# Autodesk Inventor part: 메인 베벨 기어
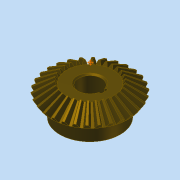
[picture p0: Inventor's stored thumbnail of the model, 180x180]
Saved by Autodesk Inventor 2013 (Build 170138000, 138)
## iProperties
Created: 2016-04
Part Number: 메인 베벨 기어
Material: 강철, 탄소
Document SubType Name: 판금
Designer: mdu
Categories: <?xml version="1.0" encoding="UTF-16"?> <MemberInstance><Categories><FamilyTemplate><FamilyTemplateParameter ValueType="xs:double" Id="1" ObjectReferenceKey="da
Mass: 269.926 g
Surface Area: 108.837 cm^2
Volume: 34.2981 cm^3
Density: 7.87 g/cm^3
Sheet Metal Rule: 기본값
CustomPartVersion: 1
Author: mdu
Revision Number: 1
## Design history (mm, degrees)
node "맨 위 점"
node "메쉬 평면2"
sketch "톱니 본체 스케치"
  geometry: L1 (0, 0)-(28.669, -21.997); L2 (28.669, -21.997)-(31.109, -18.336); L3 (31.109, -18.336)-(0, 0); L4 (30, -20)-(0, 0); L5 (17.219, -13.212)-(18.685, -11.013); L6 (28.669, -21.997)-(17.219, -13.212); L7 (31.109, -18.336)-(18.685, -11.013); L8 (0, -39.387)-(0, 6.564) reference; L9 (0, -20)-(31.109, -20)
  constraints: 16 end point, 4 point on line, 3 perpendicular, 2 collinear, 1 horizontal alignment, 1 vertical alignment
  dimensions: "d0" = 60 diameter of L4.start L8 (= da_de); "d1" = 57.33744 diameter of L1.end L8 (= da_dfe); "d2" = 62.2188 diameter of L2.end L8 (= da_dae); "d3" = 14.4 distance between parallel lines of L2 L5 (= da_b); "d4" = 18.3359 vertical distance of L2.end L1.start (= da_ve)
revolve "톱니 본체" sketch "톱니 본체 스케치" stored, may be unused: angle "d5" = 90 deg
node "시작점"
node "톱니 평면"
sketch "시작 스케치"
  geometry: L1 (0, -23.505)-(0, 10.645) reference; L2 (-0.709, -2.928)-(0.709, -2.928); A1 r 19.188 centre (-19.457, -7.014) between (-0.709, -2.928) and (-3.232, 3.229); A2 r 19.188 centre (19.457, -7.014) between (3.232, 3.229) and (0.709, -2.928); A3 r 57.403 centre (0, -54.083) between (3.232, 3.229) and (-3.232, 3.229); 1 further point
  constraints: 6 point on circle, 3 centre point, 3 symmetric about line, 2 end point, 1 coincident, 1 perpendicular, 1 other
  dimensions: "d7" = 19.18795 radius of A1 (= fd_rr); "d8" = 19.45712 horizontal distance of point (0, -54.083) A1.centre (= fd_x); "d9" = 47.06905 vertical distance of point (0, -54.083) A1.centre (= fd_y); "d57" = 57.40327 radius of A3 (= 0.5 x fd_dva + 0.3 x da_he); "d58" = 51.15527 distance from line of A3.centre L2 (= 0.5 x fd_dva - 1.12 x da_he)
node "끝점"
  node "끝 평면"
sketch "3D 스케치 오른쪽"
  node "Helical Curve Right" dims "d65" = 229.90621 (computed from da_dm, da_delta, da_beta), "d66" = 31.5, "d67" = 60 (= da_de), "d68" = -9.82794 (= -da_delta), "d69" = 8.10972 (computed from fd_loft, da_delta)
node "끝 평면 오른쪽"
sketch "끝 스케치 오른쪽"
  geometry: L1 (0, -41.54)-(0, 13.178) reference; L2 (-0.422, -1.69)-(0.422, -1.69); A1 r 11.427 centre (-11.587, -4.123) between (-0.422, -1.69) and (-1.925, 1.977); A2 r 11.427 centre (11.587, -4.123) between (1.925, 1.977) and (0.422, -1.69); A3 r 34.184 centre (0, -32.153) between (1.925, 1.977) and (-1.925, 1.977); 1 further point
  constraints: 6 point on circle, 3 centre point, 3 symmetric about line, 2 end point, 1 coincident, 1 perpendicular, 1 other
  dimensions: "d70" = 11.58699 horizontal distance of A3.centre A1.centre (computed from fd_x, fd_ratio); "d71" = 28.03028 vertical distance of point (0, -32.153) A1.centre (computed from fd_y, fd_ratio); "d72" = 11.4267 radius of A1 (computed from fd_rr, fd_ratio); "d73" = 30.46369 distance from line of point (0, -32.153) L2 (computed from d58, fd_ratio); "d74" = 34.18446 radius of A3 (computed from d57, fd_ratio)
feature "로프트 오른쪽" sketch "끝 스케치 오른쪽" dims "d75" = 0, "d77" = 0, "d79" = 0, "d80" = 90 deg, "d85" = 20, "d92" = 90 deg, "d93" = 90 deg, "da_teethtype" = 0 [user parameter]
sketch "3D 스케치 왼쪽"
  node "Helical Curve Left" dims "d26" = 229.90621 (computed from da_dm, da_delta, da_beta), "d27" = 8.10972 (computed from fd_loft, da_delta), "d28" = 60 (= da_de), "d29" = -9.82794 (= -da_delta)
node "끝 평면 왼쪽"
sketch "끝 스케치 왼쪽" dims "d56" = 10.3728 (derived)
  geometry: L1 (0, -43.753)-(0, 15.405) reference; L2 (-0.422, -1.678)-(0.422, -1.678); A1 r 11.427 centre (-11.587, -4.111) between (-0.422, -1.678) and (-1.925, 1.988); A2 r 11.427 centre (11.587, -4.111) between (1.925, 1.988) and (0.422, -1.678); A3 r 34.184 centre (0, -32.142) between (1.925, 1.988) and (-1.925, 1.988); 2 further points; 1 other entity
  constraints: 6 point on circle, 3 centre point, 3 symmetric about line, 2 end point, 1 coincident, 2 other
  dimensions: "d30" = 11.4267 radius of A1 (computed from fd_rr, fd_ratio); "d31" = 11.58699 horizontal distance of point (0, -32.142) A1.centre (computed from fd_x, fd_ratio); "d32" = 28.03028 vertical distance of A1.centre point (0, -32.142) (computed from fd_y, fd_ratio); "d61" = 34.18446 radius of A3 (computed from d57, fd_ratio); "d62" = 30.46369 distance from line of point (0, -32.142) L2 (computed from d58, fd_ratio)
feature "로프트 왼쪽" sketch "끝 스케치 왼쪽" dims "d35" = 0, "d37" = 0, "d39" = 0, "d40" = 90 deg, "d84" = 10, "d90" = 90 deg, "d91" = 90 deg, "da_teethtype" = 0 [user parameter]
sketch "본체 스케치"
  geometry: L1 (0, -35.038)-(0, -19.531) reference; L2 (28.669, -21.997)-(17.219, -13.212) reference; L3 (17.219, -13.212)-(0, -13.212); L4 (28.669, -21.997)-(0, -21.997)
  constraints: 4 end point, 2 perpendicular, 2 point on line
revolve "본체 고정" sketch "본체 스케치" stored, may be unused: angle "d46" = 90 deg
feature "피치 지름" dims angle "d47" = 90 deg
sketch "스케치8"
  geometry: C1 r 22.5 at (0, 0); 1 further point
  constraints: 1 centre point, 1 coincident
  dimensions: "d94" = 45 diameter of C1
extrude "돌출1" join sketch "스케치8" distance "d95" = 13; taper "d96" = 0 deg
sketch "스케치9"
  geometry: 1 further point
hole "구멍1" sketch "스케치9" at (0, 0) diameter "d97" = 17; stored, may be unused: countersink angle "d101" = 90 deg, drill point angle "d103" = 118 deg; dims "d98" = 6, "d99" = 4, "d100" = 2, "d102" = 8
sketch "스케치10"
  geometry: L1 (8.124, 2.5)-(10.8, 2.5); L2 (10.8, 2.5)-(10.8, -2.5); L3 (10.8, -2.5)-(8.124, -2.5); A1 r 8.5 centre (0, 0) between (8.124, 2.5) and (8.124, -2.5) reference; 1 further point
  constraints: 6 end point, 2 parallel, 2 point on circle, 1 horizontal, 1 perpendicular
  dimensions: "d104" = 5 distance of L1.end L2.end; "d112" = 19.3 dimension on A1 L2
extrude "돌출2" cut sketch "스케치10" stored distance "d106" = 10; taper "d107" = 0 deg
chamfer "모따기1" distance "d108" = 1; stored, may be unused: second distance "d109" = 2, angle "d110" = 45 deg
fillet "모깎기1" dims "d111" = 2
body "Solid1"
feature "로프트" dims "d17" = 0, "d18" = 90 deg, "d19" = 0, "d20" = 90 deg, "d89" = 0, "da_teethtype" = 0 [user parameter]
pattern_circular "원형 패턴" dims angle "d22" = 360 deg, "d88" = 0, "da_teethtype" = 0 [user parameter]
pattern_circular "원형 패턴 오른쪽" dims angle "d82" = 360 deg, "da_teethtype" = 0 [user parameter]
pattern_circular "원형 패턴 왼쪽" dims angle "d42" = 360 deg, "da_teethtype" = 0 [user parameter]
sketch "끝 스케치"
  geometry: L1 (0, -15.359)-(0, 6.983) reference; L2 (-0.422, -1.69)-(0.422, -1.69); A1 r 11.427 centre (-11.587, -4.123) between (-0.422, -1.69) and (-1.925, 1.977); A2 r 11.427 centre (11.587, -4.123) between (1.925, 1.977) and (0.422, -1.69); A3 r 34.184 centre (0, -32.153) between (1.925, 1.977) and (-1.925, 1.977); 1 further point
  constraints: 6 point on circle, 3 centre point, 3 symmetric about line, 2 end point, 1 coincident, 1 other
  dimensions: "d12" = 11.4267 radius of A1 (computed from fd_rr, fd_ratio); "d15" = 11.58699 horizontal distance of A1.centre point (0, -32.153) (computed from fd_x, fd_ratio); "d16" = 28.03028 vertical distance of A1.centre point (0, -32.153) (computed from fd_y, fd_ratio); "d59" = 34.18446 radius of A3 (computed from d57, fd_ratio); "d60" = 30.46369 distance from line of A3.centre L2 (computed from d58, fd_ratio)
sketch "Sketch6"
  geometry: L1 (30, -20)-(0, 0) reference; L2 (0, -37.8)-(0, 6.3) reference
body "Srf1"
other parameters: "da_b" = 14.4 [user parameter; used in 2 equation terms], "da_de" = 60 [user parameter; used in 4 equation terms], "da_dae" = 62.2188 [user parameter; used in 2 equation terms], "da_dfe" = 57.33744 [user parameter; used in 1 equation term], "da_le" = 36.05551 [user parameter; used in 1 equation term], "da_omega" = 90 deg [user parameter; used in 1 equation term], "da_beta" = 0 [user parameter; used in 2 equation terms], "da_delta" = 9.82794 [user parameter; used in 8 equation terms], "da_alpha" = 20 deg [user parameter; used in 2 equation terms], "da_he" = 4.4 [user parameter; used in 4 equation terms], "da_ve" = 18.3359 [user parameter; used in 1 equation term], "fd_dv" = 108.16654 (computed from da_de, da_delta) [user parameter; used in 1 equation term], "fd_dva" = 112.16654 (computed from da_dae, da_delta) [user parameter; used in 3 equation terms], "fd_dvb" = 101.6433 (computed from fd_dv, da_alpha) [user parameter; used in 2 equation terms], "da_zv" = 540.83269 [user parameter; used in 1 equation term], "fd_loft" = 14.62 (= da_b + 0.05 x da_he) [user parameter; used in 4 equation terms], "fd_ratio" = 5.95514 (computed from da_le, fd_loft) [user parameter; used in 15 equation terms], "fd_rr" = 19.18795 (computed from fd_dd, fd_dvb) [user parameter; used in 6 equation terms], "fd_angle" = 0.29367 (computed from da_zv) [user parameter; used in 4 equation terms], "fd_x1" = 1.58802 (computed from da_dvw, fd_angle) [user parameter; used in 1 equation term], "fd_y1" = 54.05995 (computed from da_dvw, fd_angle) [user parameter; used in 1 equation term], "fd_x2" = 17.8691 (computed from fd_rr, fd_angle2, fd_angle) [user parameter; used in 1 equation term], "fd_y2" = 6.9909 (computed from fd_rr, fd_angle2, fd_angle) [user parameter; used in 1 equation term], "fd_x" = 19.45712 (= fd_x1 + fd_x2) [user parameter; used in 4 equation terms], "fd_y" = 47.06905 (= fd_y1 - fd_y2) [user parameter; used in 4 equation terms], "fd_angle2" = 3.43555 (computed from fd_dvb, fd_dd, da_alpha) [user parameter; used in 2 equation terms], "fd_dd" = 108.64654 (= fd_dva - 0.8 x da_he) [user parameter; used in 2 equation terms], "da_dvw" = 108.16654 [user parameter; used in 2 equation terms], "d11" = 14.62 (= fd_loft), "da_dm" = 48.01848 [user parameter; used in 2 equation terms], "da_x" = 0 [user parameter], "da_m" = 2 [user parameter], "d48" = 0, "d49" = 0, "d50" = 90 deg (= da_omega), "d51" = 6 deg (computed from da_z), "d52" = 0, "d53" = 0, "d54" = 0, "K계수" = 4.4, "BendRadius" = 0.5 (derived), "BendReliefWidth" = 0.5 (derived), "BendReliefDepth" = 0.25 (derived), "CornerReliefSize" = 2 (derived), "SeamGap" = 0.01, "MinimumRemnant" = 1 (derived), "TransitionRadius" = 0.5 (= BendRadius)
